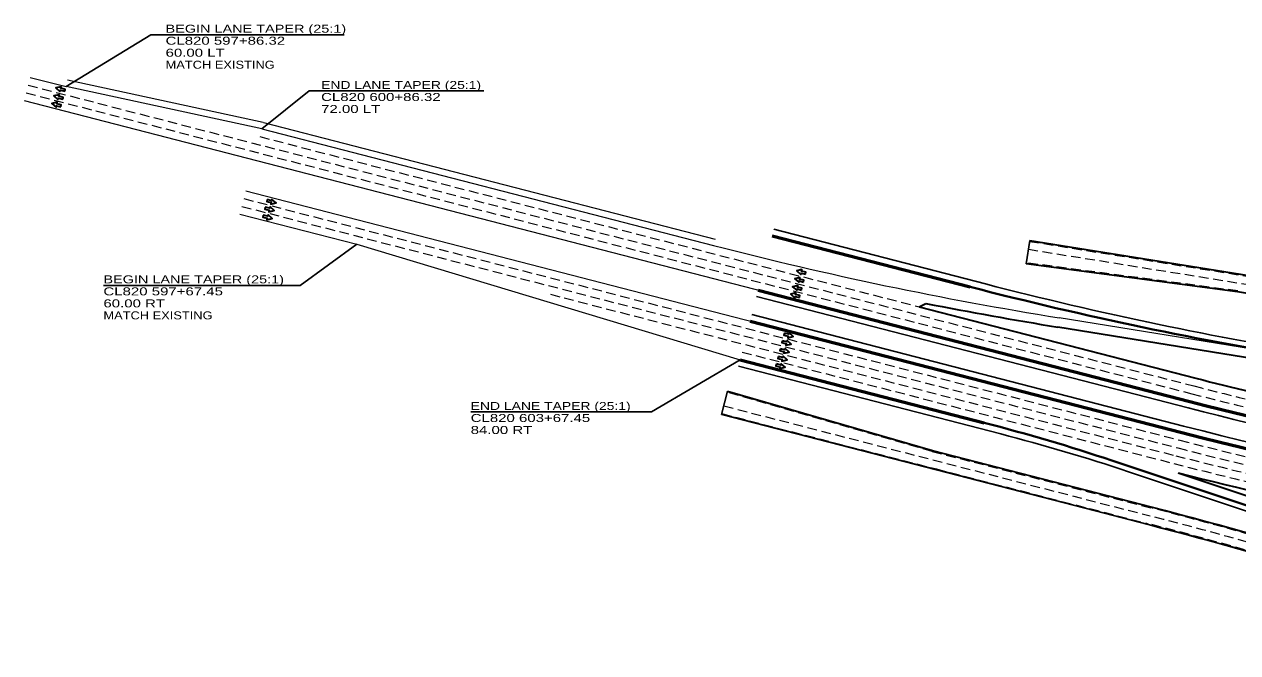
# Model space of a CAD drawing. Extents: x 2326434 to 2368642, y 6985225 to 6995090.
# Drawn here: x 2326434 to 2328254, y 6991088 to 6992031 of the extents above; entities that cross this region are included whole.
import ezdxf

# ---------------------------------------------------------------- set-up
doc = ezdxf.new("R2010")
doc.units = 0
doc.header["$LTSCALE"] = 4.8
doc.linetypes.add('MEDIUM_DASHED', pattern=[4.5, 3, -1.5])
for name, color, linetype, lineweight in [('10', 7, 'Continuous', 35), ('26', 7, 'Continuous', 25), ('27', 7, 'Continuous', 25), ('28', 7, 'Continuous', 25), ('40', 7, 'Continuous', 35), ('5', 7, 'Continuous', 25), ('50', 7, 'MEDIUM_DASHED', 13)]:
    doc.layers.add(name, color=color, linetype=linetype, lineweight=lineweight)

msp = doc.modelspace()

# ---------------------------------------------------------------- linework, layer by layer
at = {"layer": '10'}
for p, q in [((2327776.763, 6991607.077), (2327786.684, 6991612.246)), ((2327776.763, 6991607.077), (2328191.721, 6991500.021)), ((2328369.448, 6991514.635), (2327984.637, 6991576.735)), ((2328165.164, 6991358.166), (2328441.301, 6991265.951))]:
    msp.add_line(p, q, dxfattribs=at)
for centre, radius, start, end in [((2328899.675, 6997246.954), 5743.578, 258.82653, 260.83287), ((2329611.03, 6997001.375), 5681.49, 255.53357, 257.24941), ((2329611.03, 6997001.375), 5825.49, 255.62919, 258.47273)]:
    msp.add_arc(centre, radius, start, end, dxfattribs=at)
at = {"layer": '26'}
for p, q in [((2327558.405, 6991723.311), (2327876.179, 6991641.328)), ((2327532.424, 6991622.608), (2328180.23, 6991455.479)), ((2327525.43, 6991595.496), (2328173.235, 6991428.367)), ((2327505.445, 6991518.033), (2327898.997, 6991416.499))]:
    msp.add_line(p, q, dxfattribs=at)
at = {"layer": '26', "lineweight": 53}
for p, q in [((2327555.907, 6991713.628), (2327853.161, 6991636.939)), ((2327534.923, 6991632.291), (2328182.728, 6991465.162)), ((2327522.932, 6991585.813), (2328170.737, 6991418.684)), ((2327507.943, 6991527.716), (2327874.071, 6991433.257))]:
    msp.add_line(p, q, dxfattribs=at)
at = {"layer": '26'}
for radius, end in [(5727.49, 270.53529), (5755.49, 264.94912)]:
    msp.add_arc((2329611.03, 6997001.375), radius, 255.53357, end, dxfattribs=at)
at = {"layer": '26', "lineweight": 53}
for radius, end in [(5717.49, 270.53529), (5765.49, 264.94912)]:
    msp.add_arc((2329611.03, 6997001.375), radius, 255.53357, end, dxfattribs=at)
at = {"layer": '27', "lineweight": 40}
msp.add_line((2328065.83, 6991376.578), (2328604.266, 6991196.77), dxfattribs=at)
at = {"layer": '27'}
msp.add_line((2328090.756, 6991359.82), (2328601.732, 6991189.182), dxfattribs=at)
at = {"layer": '27', "lineweight": 40}
for centre, radius, start, end in [((2329284.483, 6997184.856), 5729.578, 255.53357, 260.83288), ((2327158.41, 6988659.299), 2864.789, 71.53355, 75.53357)]:
    msp.add_arc(centre, radius, start, end, dxfattribs=at)
at = {"layer": '27'}
for centre, radius, start, end in [((2329307.501, 6997189.245), 5729.578, 255.53357, 260.83288), ((2327183.336, 6988642.541), 2864.789, 71.53355, 75.53357)]:
    msp.add_arc(centre, radius, start, end, dxfattribs=at)
at = {"layer": '28'}
for p, q in [((2327942.552, 6991706.715), (2327936.932, 6991671.618)), ((2327942.473, 6991706.221), (2328644.01, 6991593.884)), ((2327942.552, 6991706.715), (2328644.089, 6991594.378)), ((2328254.258, 6991629.458), (2327936.932, 6991671.618)), ((2328254.323, 6991629.953), (2327936.998, 6991672.114)), ((2328254.258, 6991629.458), (2328639.82, 6991567.718)), ((2328254.337, 6991629.951), (2328639.899, 6991568.211)), ((2327489.157, 6991480.405), (2327480.152, 6991445.504)), ((2327796.613, 6991391.227), (2327489.018, 6991479.925)), ((2327796.751, 6991391.708), (2327489.157, 6991480.405)), ((2327796.626, 6991391.224), (2328126.54, 6991306.109)), ((2327796.751, 6991391.708), (2328126.665, 6991306.593))]:
    msp.add_line(p, q, dxfattribs=at)
for points in [[(2327480.152, 6991445.504), (2327802.038, 6991362.46), (2328119.92, 6991280.449)], [(2327480.277, 6991445.988), (2327802.163, 6991362.944), (2328120.045, 6991280.933)]]:
    msp.add_lwpolyline(points, dxfattribs=at)
for radius in [6586.695, 6587.195, 6560.195, 6560.695]:
    msp.add_arc((2326481.102, 6984928.249), radius, 69.88799, 75.53359, dxfattribs=at)
at = {"layer": '40'}
for points in [[(2326491.923, 6991918.281), (2326492.65, 6991921.192), (2326486.046, 6991922.842), (2326486.637, 6991925.206), (2326478.736, 6991923.285), (2326484.806, 6991917.874), (2326485.319, 6991919.93)], [(2326494.989, 6991930.28), (2326495.716, 6991933.192), (2326489.112, 6991934.841), (2326489.703, 6991937.206), (2326481.802, 6991935.284), (2326487.872, 6991929.873), (2326488.385, 6991931.93)], [(2326489.004, 6991907.068), (2326489.731, 6991909.979), (2326483.127, 6991911.629), (2326483.718, 6991913.993), (2326475.817, 6991912.072), (2326481.887, 6991906.661), (2326482.4, 6991908.717)], [(2326798.761, 6991767.841), (2326798.034, 6991764.93), (2326804.638, 6991763.281), (2326804.048, 6991760.916), (2326811.949, 6991762.837), (2326805.879, 6991768.248), (2326805.365, 6991766.192)], [(2326792.776, 6991744.629), (2326792.049, 6991741.718), (2326798.653, 6991740.068), (2326798.063, 6991737.704), (2326805.964, 6991739.625), (2326799.894, 6991745.036), (2326799.38, 6991742.98)], [(2326795.842, 6991756.628), (2326795.115, 6991753.717), (2326801.719, 6991752.068), (2326801.129, 6991749.703), (2326809.03, 6991751.625), (2326802.96, 6991757.035), (2326802.446, 6991754.979)], [(2327603.068, 6991644.234), (2327603.796, 6991647.145), (2327597.192, 6991648.794), (2327597.782, 6991651.159), (2327589.881, 6991649.237), (2327595.951, 6991643.827), (2327596.465, 6991645.883)], [(2327606.11, 6991655.959), (2327606.837, 6991658.871), (2327600.233, 6991660.52), (2327600.824, 6991662.885), (2327592.922, 6991660.963), (2327598.992, 6991655.552), (2327599.506, 6991657.609)], [(2327600.002, 6991632.234), (2327600.729, 6991635.145), (2327594.125, 6991636.795), (2327594.716, 6991639.159), (2327586.815, 6991637.238), (2327592.885, 6991631.827), (2327593.398, 6991633.883)], [(2327597.083, 6991621.021), (2327597.81, 6991623.933), (2327591.206, 6991625.582), (2327591.797, 6991627.947), (2327583.896, 6991626.025), (2327589.966, 6991620.614), (2327590.479, 6991622.671)], [(2327574.442, 6991567.513), (2327573.715, 6991564.602), (2327580.319, 6991562.952), (2327579.728, 6991560.588), (2327587.629, 6991562.509), (2327581.559, 6991567.92), (2327581.046, 6991565.864)], [(2327568.457, 6991544.301), (2327567.73, 6991541.389), (2327574.334, 6991539.74), (2327573.743, 6991537.375), (2327581.644, 6991539.297), (2327575.574, 6991544.708), (2327575.061, 6991542.651)], [(2327571.523, 6991556.3), (2327570.796, 6991553.389), (2327577.4, 6991551.739), (2327576.809, 6991549.375), (2327584.71, 6991551.296), (2327578.64, 6991556.707), (2327578.127, 6991554.651)], [(2327562.543, 6991521.369), (2327561.816, 6991518.457), (2327568.42, 6991516.808), (2327567.829, 6991514.443), (2327575.731, 6991516.365), (2327569.661, 6991521.776), (2327569.147, 6991519.719)], [(2327565.415, 6991532.575), (2327564.688, 6991529.663), (2327571.292, 6991528.014), (2327570.701, 6991525.649), (2327578.603, 6991527.571), (2327572.533, 6991532.982), (2327572.019, 6991530.925)]]:
    msp.add_lwpolyline(points, close=True, dxfattribs=at)
at = {"layer": '5'}
for p, q in [((2326914.056, 6992015.137), (2326646.258, 6992015.137)), ((2327123.546, 6991930.736), (2326879.562, 6991930.736)), ((2326820.812, 6991639.263), (2326553.014, 6991639.263)), ((2327347.9, 6991449.42), (2327103.916, 6991449.42))]:
    msp.add_line(p, q, dxfattribs=at)
for points in [[(2326646.258, 6992015.137), (2326624.193, 6992015.137), (2326497.061, 6991937.231)], [(2326879.562, 6991930.736), (2326861.828, 6991930.736), (2326790.547, 6991873.906)], [(2326820.812, 6991639.263), (2326848.15, 6991639.263), (2326932.962, 6991700.842)], [(2327347.9, 6991449.42), (2327375.125, 6991449.42), (2327507.943, 6991527.716)]]:
    msp.add_lwpolyline(points, dxfattribs=at)
at = {"layer": '50', "linetype": 'Continuous'}
for p, q in [((2326443.276, 6991951.107), (2326497.061, 6991937.231)), ((2326792.657, 6991883.681), (2326499.171, 6991947.006)), ((2326790.547, 6991873.906), (2326497.061, 6991937.231)), ((2326434.283, 6991916.248), (2328182.728, 6991465.162)), ((2326790.547, 6991873.906), (2327468.353, 6991699.038)), ((2326793.046, 6991883.589), (2327470.851, 6991708.72)), ((2326766.565, 6991780.95), (2328170.737, 6991418.684)), ((2326757.572, 6991746.092), (2326932.962, 6991700.842)), ((2326932.962, 6991700.842), (2327507.943, 6991527.716)), ((2328415.565, 6991521.374), (2327986.868, 6991590.556))]:
    msp.add_line(p, q, dxfattribs=at)
at = {"layer": '50'}
for p, q in [((2326437.281, 6991927.868), (2328185.726, 6991476.782)), ((2326440.279, 6991939.487), (2328188.723, 6991488.401)), ((2326787.55, 6991862.287), (2327776.763, 6991607.077)), ((2326763.568, 6991769.331), (2328167.739, 6991407.065)), ((2326760.57, 6991757.711), (2328164.741, 6991395.445)), ((2327942.315, 6991705.234), (2328643.852, 6991592.897)), ((2327940.418, 6991693.385), (2328641.955, 6991581.048)), ((2328254.455, 6991630.944), (2327937.13, 6991673.105)), ((2327223.45, 6991625.899), (2328161.744, 6991383.826)), ((2327510.941, 6991539.335), (2328158.746, 6991372.206)), ((2327796.336, 6991390.267), (2327488.741, 6991478.964)), ((2327483.525, 6991458.576), (2328123.292, 6991293.521)), ((2327796.377, 6991390.255), (2328126.29, 6991305.14))]:
    msp.add_line(p, q, dxfattribs=at)
msp.add_lwpolyline([(2327480.527, 6991446.956), (2327802.413, 6991363.912), (2328120.295, 6991281.901)], dxfattribs=at)
at = {"layer": '50', "linetype": 'Continuous'}
msp.add_arc((2328899.675, 6997246.954), 5729.578, 255.53357, 260.83287, dxfattribs=at)
at = {"layer": '50'}
for centre, radius, start, end in [((2329611.03, 6997001.375), 5693.49, 255.53357, 270.53529), ((2329611.03, 6997001.375), 5705.49, 255.53357, 270.53529), ((2329611.03, 6997001.375), 5789.49, 255.53357, 270.53529), ((2329611.03, 6997001.375), 5777.49, 255.53357, 270.53529), ((2329611.03, 6997001.375), 5801.49, 255.53357, 270.53529), ((2329611.03, 6997001.375), 5813.49, 255.53357, 270.53529), ((2326481.102, 6984928.249), 6585.695, 69.88799, 75.53359), ((2326481.102, 6984928.249), 6573.695, 69.88799, 75.53359), ((2326481.102, 6984928.249), 6561.695, 69.88799, 75.53359)]:
    msp.add_arc(centre, radius, start, end, dxfattribs=at)

# ---------------------------------------------------------------- texts
at = {"layer": '5'}
for s, width, p in [('BEGIN LANE TAPER (25:1)', 1.35, (2326646.258, 6992018.137)), ('CL820 597+86.32 ', 1.4, (2326646.258, 6992000.137)), ('60.00 LT', 1.4, (2326646.258, 6991982.137)), ('MATCH EXISTING', 1.2, (2326646.258, 6991964.137)), ('END LANE TAPER (25:1)', 1.3, (2326879.562, 6991933.736)), ('CL820 600+86.32 ', 1.4, (2326879.562, 6991915.736)), ('72.00 LT', 1.4, (2326879.562, 6991897.736)), ('BEGIN LANE TAPER (25:1)', 1.35, (2326553.014, 6991642.263)), ('CL820 597+67.45 ', 1.4, (2326553.014, 6991624.263)), ('60.00 RT', 1.4, (2326553.014, 6991606.263)), ('MATCH EXISTING', 1.2, (2326553.014, 6991588.263)), ('END LANE TAPER (25:1)', 1.3, (2327103.916, 6991452.42)), ('CL820 603+67.45 ', 1.4, (2327103.916, 6991434.42)), ('84.00 RT', 1.4, (2327103.916, 6991416.42))]:
    msp.add_text(s, height=12, dxfattribs=dict(at, width=width)).set_placement(p)

doc.saveas('drawing.dxf')
